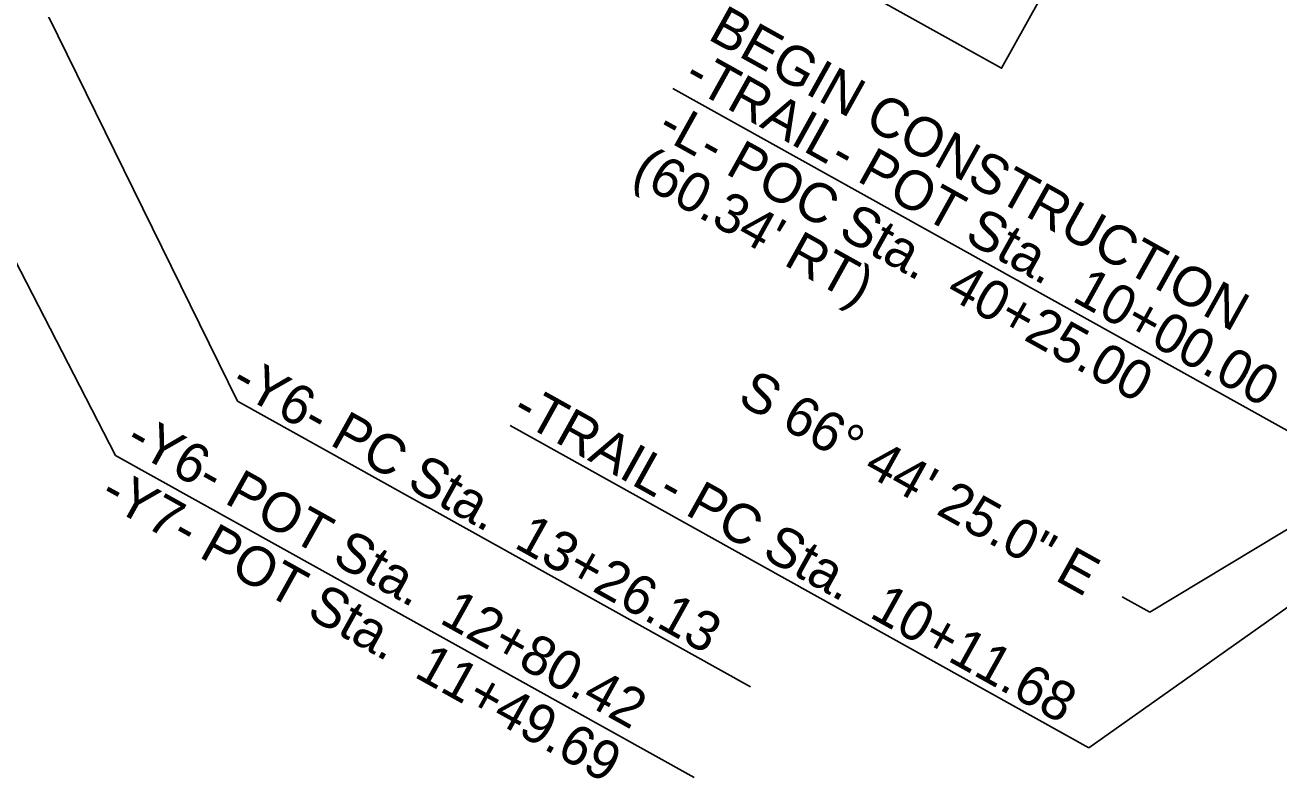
# Model space of a CAD drawing. Extents: x 1762196 to 1766326, y 709922 to 713142.
# Drawn here: x 1764158 to 1764380.6, y 710877.2 to 711011.1 of the extents above; entities that cross this region are included whole.
import ezdxf

# ---------------------------------------------------------------- set-up
doc = ezdxf.new("R2010")
doc.units = 0
for name, color, linetype in [('Pattern 1', 7, 'Continuous'), ('Pattern 2', 7, 'Continuous'), ('Prop Conc 2ft 6in Curb and Gutter', 7, 'Continuous'), ('Prop Dimension', 7, 'Continuous'), ('Prop EOT', 7, 'Continuous'), ('Prop Horizontal Alignment', 7, 'Continuous'), ('Prop Horizontal Alignment Direction Label', 7, 'Continuous'), ('Prop Horizontal Alignment Station Label', 7, 'Continuous'), ('Prop Lane Lines', 7, 'Continuous')]:
    doc.layers.add(name, color=color, linetype=linetype)

msp = doc.modelspace()

# ---------------------------------------------------------------- linework, layer by layer
at = {"layer": 'Pattern 1'}
for centre, radius, start, end in [((1765296.46, 712280.56), 1468.5, 220.01407, 240.8436), ((1765296.46, 712280.56), 1473.5, 220.01407, 240.8436), ((1765306.57, 712293.87), 1543.05, 224.81689, 240.93056), ((1765306.57, 712293.87), 1548.05, 224.8166, 240.93028)]:
    msp.add_arc(centre, radius, start, end, dxfattribs=at)
at = {"layer": 'Pattern 2'}
for radius, start in [(1468.5, 220.01407), (1473.5, 220.01407), (1526.5, 224.72992), (1531.5, 224.72992)]:
    msp.add_arc((1765296.46, 712280.56), radius, start, 240.8436, dxfattribs=at)
at = {"layer": 'Prop Conc 2ft 6in Curb and Gutter'}
for radius, start in [(1478, 220.01407), (1522, 224.72992)]:
    msp.add_arc((1765296.46, 712280.56), radius, start, 240.8436, dxfattribs=at)
at = {"layer": 'Prop Dimension'}
msp.add_lwpolyline([(1764286.28, 711044.12), (1764338.01, 711015.32), (1764331.4, 711003.44), (1764279.67, 711032.25)], close=True, dxfattribs=at)
at = {"layer": 'Prop EOT'}
for radius, start in [(1480, 220.01407), (1520, 224.72992)]:
    msp.add_arc((1765296.46, 712280.56), radius, start, 240.8436, dxfattribs=at)
at = {"layer": 'Prop Horizontal Alignment'}
msp.add_arc((1765296.46, 712280.56), 1500, 216.32502, 240.8436, dxfattribs=at)
at = {"layer": 'Prop Horizontal Alignment Station Label'}
for p, q in [((1764068.39, 711203.33), (1764195.76, 710944.38)), ((1764058.52, 711158.7), (1764174.11, 710934.74)), ((1764389.43, 710935.03), (1764273.03, 710999.86)), ((1764456.64, 710966.64), (1764357.72, 710906.93)), ((1764462.01, 710964.34), (1764346.9, 710882.83)), ((1764286.79, 710893.68), (1764195.76, 710944.38)), ((1764346.9, 710882.83), (1764244.13, 710940.06)), ((1764276.79, 710877.56), (1764174.11, 710934.74)), ((1764357.72, 710906.93), (1764352.82, 710909.66))]:
    msp.add_line(p, q, dxfattribs=at)
at = {"layer": 'Prop Lane Lines'}
msp.add_arc((1765296.46, 712280.56), 1494, 222.11492, 240.8436, dxfattribs=at)

# ---------------------------------------------------------------- texts
at = {"layer": 'Prop Horizontal Alignment Direction Label'}
msp.add_text('S 66%%d 44\' 25.0" E', height=7, rotation=330.8875, dxfattribs=at).set_placement((1764284.25, 710944.12))
at = {"layer": 'Prop Horizontal Alignment Station Label'}
for s, p in [('BEGIN CONSTRUCTION', (1764279.02, 711008.69)), ('-TRAIL- POT Sta.  10+00.00', (1764274.59, 711000.74)), ('-L- POC Sta.  40+25.00', (1764269.88, 710991.67)), ("(60.34' RT)", (1764265.45, 710983.72)), ('-Y6- PC Sta.  13+26.13', (1764194.19, 710946.6)), ('-TRAIL- PC Sta.  10+11.68', (1764244.09, 710941.57)), ('-Y6- POT Sta.  12+80.42', (1764175.48, 710936.26)), ('-Y7- POT Sta.  11+49.69', (1764170.97, 710926.69))]:
    msp.add_text(s, height=7, rotation=330.8875, dxfattribs=at).set_placement(p)

doc.saveas('drawing.dxf')
